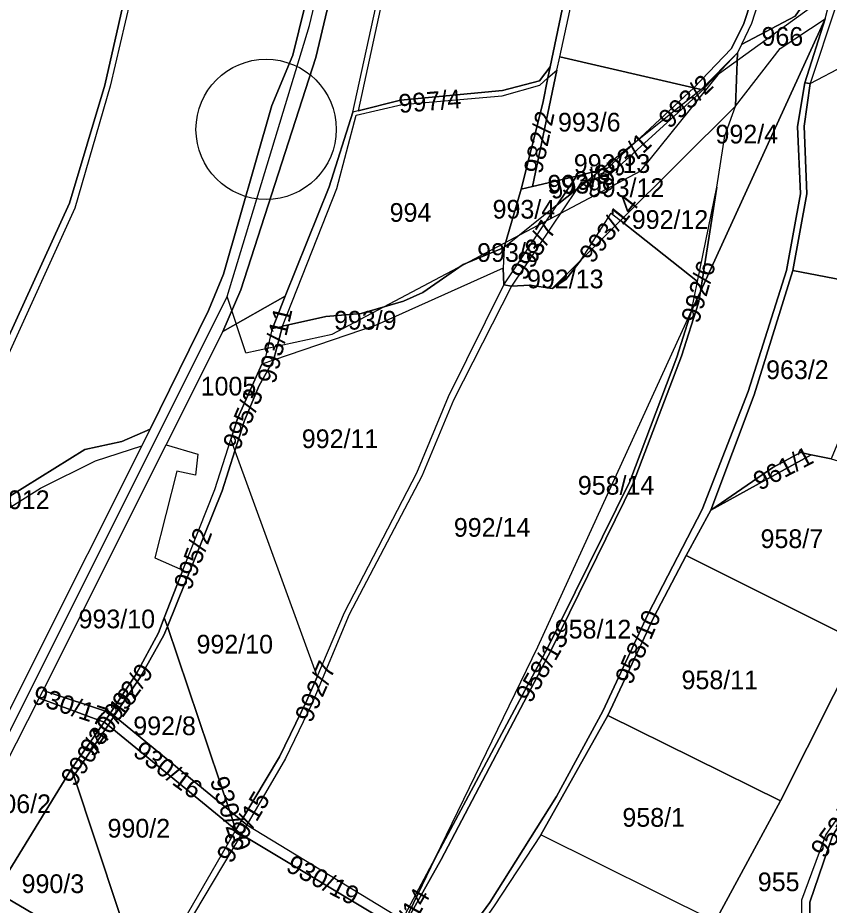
# Model space of a CAD drawing. Extents: x -623250 to -619626, y -1079612 to -1075424.
# Drawn here: x -622121.5 to -621687.6, y -1079113.5 to -1078639.2 of the extents above; entities that cross this region are included whole.
import ezdxf

# ---------------------------------------------------------------- set-up
doc = ezdxf.new("R2010")
doc.units = 0
for name, color, linetype in [('Bodové pole k revizi', 7, 'Continuous'), ('Cestní síť', 7, 'Continuous'), ('Hranice šetřená (k_ú_Džbánov - vnitřní obvod)', 7, 'Continuous'), ('Parcela nároku', 7, 'Continuous'), ('Parcelní číslo', 7, 'Continuous'), ('Silnice III_35719', 7, 'Continuous')]:
    doc.layers.add(name, color=color, linetype=linetype)

msp = doc.modelspace()

# ---------------------------------------------------------------- linework, layer by layer
at = {"layer": 'Bodové pole k revizi'}
msp.add_circle((-621988.75, -1078698.85), 37.5, dxfattribs=at)
at = {"layer": 'Cestní síť'}
for p, q in [((-621746.25, -1078668.89), (-621693.23, -1078630.58)), ((-621788.46, -1078720.96), (-621746.25, -1078668.89)), ((-621953.4, -1078808.38), (-621788.46, -1078720.96)), ((-621999.54, -1078818.21), (-622009.59, -1078788.2)), ((-621999.54, -1078818.21), (-621953.4, -1078808.38))]:
    msp.add_line(p, q, dxfattribs=at)
at = {"layer": 'Hranice šetřená (k_ú_Džbánov - vnitřní obvod)'}
for points in [[(-622051.23, -1079158.54), (-622001.9, -1079075.76), (-621918.53, -1079125.72)], [(-622133.2, -1079106.32), (-622055.86, -1079151.87)]]:
    msp.add_lwpolyline(points, dxfattribs=at)
at = {"layer": 'Parcela nároku'}
for points in [[(-621798.7, -1078125.48), (-621844.4, -1078219.47), (-621874.38, -1078283.8), (-621900.59, -1078357.45), (-621904.78, -1078375.94), (-621939.56, -1078517.46), (-621974.55, -1078659.27), (-621985.66, -1078686.13), (-622011.55, -1078776.25), (-622019.48, -1078795.6), (-622050.66, -1078859.01), (-622055.18, -1078868.03), (-622113.39, -1078984.18), (-622171.75, -1079100.51)], [(-621920.88, -1078143.42), (-621992.93, -1078299.5), (-622012.94, -1078348.91), (-622023.83, -1078386.03), (-622051.57, -1078572.25), (-622075, -1078675.16), (-622093.94, -1078738.39), (-622132.06, -1078821.5), (-622164.4, -1078884.44), (-622184.48, -1078918.47), (-622193.37, -1078930.2), (-622224.32, -1078909.51), (-622245.47, -1078895.87), (-622260.65, -1078888.33), (-622247.8, -1078862.64), (-622201.27, -1078777.95), (-622154.33, -1078663.49), (-622142.85, -1078603.35), (-622129.1, -1078527.57), (-622121.6, -1078479.86), (-622105.64, -1078380), (-622059.07, -1078244.77), (-622006.23, -1078130.73)], [(-621536.14, -1078141.02), (-621601.13, -1078271), (-621640.24, -1078349.18), (-621682.14, -1078455.7), (-621692.39, -1078499.68), (-621716.55, -1078591.12), (-621733.53, -1078642.87), (-621740.16, -1078655.75), (-621760.1, -1078676.68), (-621831.78, -1078660.02), (-621818.81, -1078600.9), (-621799.45, -1078520.18), (-621780.85, -1078451.5), (-621768.67, -1078415.18), (-621763.22, -1078400.52), (-621737.43, -1078338.4), (-621720.36, -1078292.56), (-621706.68, -1078264.18), (-621667.8, -1078192.73)], [(-622132.06, -1078821.5), (-622093.94, -1078738.39), (-622075, -1078675.16), (-622051.57, -1078572.25), (-622023.83, -1078386.03), (-622012.94, -1078348.91), (-621992.93, -1078299.5), (-621920.88, -1078143.42)], [(-621917.7, -1078144.04), (-621989.81, -1078300.86), (-622009.81, -1078350.99), (-622020.37, -1078386.11), (-622048.13, -1078572.96), (-622072.14, -1078675.77), (-622091.03, -1078741.03), (-622128.19, -1078823.01)], [(-621915.38, -1078144.86), (-621987.87, -1078301.69), (-622007.96, -1078351.4), (-622018.08, -1078386.56), (-622033.09, -1078484.64), (-622048.13, -1078572.96), (-622072.14, -1078675.77), (-622091.03, -1078741.03), (-622128.19, -1078823.01)], [(-622158.74, -1079098.38), (-622110.04, -1079002.85), (-622107.93, -1078998.74), (-622042.21, -1078867.47), (-622011.88, -1078806.98), (-622002.29, -1078784.69), (-621962.09, -1078660.47), (-621921.42, -1078488.75), (-621894.99, -1078378.08), (-621888.3, -1078355.01), (-621885.08, -1078343.91), (-621863.53, -1078286.56), (-621830.24, -1078215.74), (-621800.25, -1078151.95)], [(-622142.01, -1078904.85), (-622085.75, -1078869.99), (-622065.84, -1078865.65), (-622050.66, -1078859.01), (-622019.48, -1078795.6), (-622011.55, -1078776.25), (-621985.66, -1078686.13), (-621974.55, -1078659.27), (-621939.56, -1078517.46), (-621904.78, -1078375.94), (-621923.56, -1078371.78), (-621935.88, -1078364.97), (-621896.45, -1078279.61), (-621893.72, -1078261.43), (-621874.57, -1078216.88), (-621849.93, -1078182.93)], [(-621673.38, -1078190.19), (-621712.52, -1078262.15), (-621725.93, -1078289.46), (-621734.43, -1078314.47), (-621736.18, -1078319.06), (-621772.93, -1078413.68), (-621784.46, -1078450.78), (-621803.29, -1078519.05), (-621823.3, -1078600.54), (-621836.88, -1078665.49), (-621838.04, -1078671.32), (-621833.28, -1078667.16), (-621831.78, -1078660.02), (-621818.81, -1078600.9), (-621799.45, -1078520.18), (-621780.85, -1078451.5), (-621768.67, -1078415.18), (-621763.22, -1078400.52), (-621722.25, -1078292.55), (-621708.86, -1078263.97), (-621670.16, -1078192.45)], [(-621684.21, -1078633.08), (-621697.9, -1078674.4), (-621700.7, -1078674.01), (-621689.88, -1078639.73), (-621682.64, -1078612.21)], [(-621572.26, -1078636.28), (-621584.71, -1078668.69), (-621592.06, -1078680.24), (-621602.02, -1078707.55), (-621608.59, -1078730.53), (-621617.46, -1078825.31), (-621625.18, -1078859.11), (-621639.04, -1078905.08), (-621650.82, -1078932.47), (-621662.97, -1078969.66), (-621668.08, -1078993.89), (-621668.45, -1079019.15), (-621676.11, -1079060.58), (-621685.97, -1079076.42), (-621698.06, -1079111.98), (-621697.69, -1079138.49)]]:
    msp.add_lwpolyline(points, dxfattribs=at)
for points in [[(-621851, -1078335.41), (-621875.98, -1078412.38), (-621889.02, -1078460.29), (-621914.51, -1078573.82), (-621939.52, -1078688.9), (-621916.93, -1078683.27), (-621862.33, -1078678.06), (-621842.5, -1078672.85), (-621836.88, -1078665.49), (-621823.3, -1078600.54), (-621803.29, -1078519.05), (-621784.46, -1078450.78), (-621772.93, -1078413.68), (-621736.18, -1078319.06), (-621786.12, -1078256.36), (-621808.67, -1078231.35), (-621826.5, -1078270.98), (-621842.49, -1078311.78)], [(-621894.99, -1078378.08), (-621921.42, -1078488.75), (-621962.09, -1078660.47), (-622002.29, -1078784.69), (-622011.88, -1078806.98), (-621978.6, -1078788.09), (-621955.11, -1078729.51), (-621942.41, -1078689.62), (-621916.87, -1078572.97), (-621891.12, -1078458.9), (-621878.16, -1078411.57), (-621853.26, -1078333.49), (-621867.46, -1078311.76), (-621888.3, -1078355.01)], [(-621843.79, -1078311.14), (-621842.49, -1078311.78), (-621851, -1078335.41), (-621875.98, -1078412.38), (-621889.02, -1078460.29), (-621914.51, -1078573.82), (-621939.52, -1078688.9), (-621942.41, -1078689.62), (-621916.87, -1078572.97), (-621891.12, -1078458.9), (-621878.16, -1078411.57), (-621853.26, -1078333.49)], [(-621716.55, -1078591.12), (-621692.39, -1078499.68), (-621682.14, -1078455.7), (-621678.32, -1078456.03), (-621688.19, -1078499.85), (-621713.01, -1078591.84), (-621729.26, -1078642.23), (-621734.51, -1078653.51), (-621736.66, -1078657.94), (-621756.17, -1078677.59), (-621760.1, -1078676.68), (-621740.16, -1078655.75), (-621733.53, -1078642.87)], [(-621678.32, -1078456.03), (-621688.19, -1078499.85), (-621713.01, -1078591.84), (-621729.26, -1078642.23), (-621734.51, -1078653.51), (-621705.92, -1078638.39), (-621694.79, -1078622.32), (-621693.69, -1078604.02), (-621688.23, -1078594.08), (-621676.74, -1078582.76), (-621665.21, -1078560.88), (-621662.89, -1078553.59), (-621659.96, -1078529.07), (-621668.93, -1078457.17), (-621674.85, -1078456.45)], [(-621659.89, -1078641.88), (-621634.19, -1078619.47), (-621563.27, -1078549.01), (-621592.52, -1078630.82), (-621603.36, -1078669.93), (-621611.72, -1078708.1), (-621622.67, -1078748.23), (-621659.71, -1078778.43), (-621673.47, -1078778.15), (-621677.73, -1078797.56), (-621660.27, -1078811.32), (-621677.88, -1078804.44), (-621679.12, -1078795.35), (-621676.5, -1078780.22), (-621707.18, -1078774.3), (-621699.61, -1078733.28), (-621701.12, -1078697.21), (-621697.9, -1078674.4), (-621679.48, -1078664.79)], [(-621693.69, -1078604.02), (-621694.79, -1078622.32), (-621705.92, -1078638.39), (-621734.51, -1078653.51), (-621736.66, -1078657.94), (-621737.8, -1078686.43), (-621713.91, -1078655.66), (-621689.88, -1078639.73), (-621682.64, -1078612.21), (-621678.01, -1078602.15), (-621676.74, -1078582.76), (-621688.23, -1078594.08)], [(-621684.21, -1078633.08), (-621697.9, -1078674.4), (-621679.48, -1078664.79), (-621659.89, -1078641.88), (-621634.19, -1078619.47), (-621628.01, -1078579.6)], [(-621895.17, -1079089.04), (-621836.16, -1078976.93), (-621792.43, -1078887.96), (-621766.57, -1078820.15), (-621757.53, -1078791.64), (-621756.55, -1078785.48), (-621689.88, -1078639.73), (-621700.7, -1078674.01), (-621704.7, -1078697.39), (-621702.94, -1078733.24), (-621710.44, -1078774.25), (-621730.96, -1078839.05), (-621755.54, -1078901.97), (-621784.5, -1078957.71), (-621808.65, -1079009.85), (-621833.45, -1079055.51), (-621869.06, -1079112.05), (-621888.44, -1079138.25), (-621913.94, -1079122.45)], [(-621743.4, -1078702.37), (-621737.8, -1078686.43), (-621713.91, -1078655.66), (-621689.88, -1078639.73), (-621756.55, -1078785.48), (-621747.73, -1078729.74)], [(-621804.3, -1078722.39), (-621817.17, -1078726.47), (-621822.84, -1078731.01), (-621857.59, -1078782.67), (-621847.83, -1078782.19), (-621835.78, -1078783.93), (-621820.34, -1078768.57), (-621804.22, -1078743.71), (-621799.29, -1078747.62), (-621737.8, -1078686.43), (-621736.66, -1078657.94), (-621756.41, -1078678.95)], [(-621809.67, -1078720.46), (-621817.17, -1078726.47), (-621804.3, -1078722.39), (-621756.41, -1078678.95), (-621736.66, -1078657.94), (-621756.17, -1078677.59), (-621791.31, -1078705.75), (-621806.14, -1078719.56)], [(-621846.36, -1078729.47), (-621833.28, -1078667.16), (-621831.78, -1078660.02), (-621760.1, -1078676.68), (-621791.31, -1078705.75), (-621809.67, -1078720.46), (-621822.84, -1078723.82)], [(-621916.93, -1078683.27), (-621939.52, -1078688.9), (-621942.41, -1078689.62), (-621955.11, -1078729.51), (-621978.6, -1078788.09), (-621985.37, -1078805.28), (-621980.07, -1078804.09), (-621950.91, -1078730.51), (-621940.55, -1078691.35), (-621915.93, -1078685.62), (-621862.53, -1078680.96), (-621842.43, -1078675.16), (-621838.04, -1078671.32), (-621836.88, -1078665.49), (-621842.5, -1078672.85), (-621862.33, -1078678.06)], [(-621840.72, -1078684.79), (-621838.04, -1078671.32), (-621833.28, -1078667.16), (-621846.36, -1078729.47), (-621852.4, -1078730.75)], [(-621915.93, -1078685.62), (-621862.53, -1078680.96), (-621842.43, -1078675.16), (-621838.04, -1078671.32), (-621840.72, -1078684.79), (-621852.4, -1078730.75), (-621861.44, -1078761.94), (-621883.45, -1078771.01), (-621905, -1078786.02), (-621915.36, -1078790.74), (-621938, -1078797.3), (-621956.9, -1078798.88), (-621980.07, -1078804.09), (-621950.91, -1078730.51), (-621940.55, -1078691.35)], [(-621710.44, -1078774.25), (-621702.94, -1078733.24), (-621704.7, -1078697.39), (-621700.7, -1078674.01), (-621697.9, -1078674.4), (-621701.12, -1078697.21), (-621699.61, -1078733.28), (-621707.18, -1078774.3), (-621727.78, -1078840.72), (-621750.95, -1078902.37), (-621764.15, -1078926.59), (-621781.51, -1078959.58), (-621805.98, -1079012.11), (-621841.81, -1079075.9), (-621866.77, -1079113.8), (-621885.5, -1079140.85), (-621888.44, -1079138.25), (-621869.06, -1079112.05), (-621833.45, -1079055.51), (-621808.65, -1079009.85), (-621784.5, -1078957.71), (-621755.54, -1078901.97), (-621730.96, -1078839.05)], [(-621791.31, -1078705.75), (-621760.1, -1078676.68), (-621756.17, -1078677.59)], [(-621737.8, -1078686.43), (-621799.29, -1078747.62), (-621758.09, -1078780.24), (-621747.73, -1078729.74), (-621743.4, -1078702.37)], [(-621791.31, -1078705.75), (-621809.67, -1078720.46), (-621806.14, -1078719.56)], [(-621822.84, -1078723.82), (-621809.67, -1078720.46), (-621817.17, -1078726.47), (-621820.49, -1078727.52), (-621822.84, -1078731.01), (-621833.16, -1078739.28)], [(-621846.36, -1078729.47), (-621822.84, -1078723.82), (-621833.16, -1078739.28), (-621861.44, -1078761.94), (-621852.4, -1078730.75)], [(-621817.17, -1078726.47), (-621820.49, -1078727.52), (-621822.84, -1078731.01)], [(-621761.29, -1078795.84), (-621758.09, -1078780.24), (-621747.73, -1078729.74), (-621756.55, -1078785.48)], [(-621861.67, -1078781.98), (-621833.16, -1078739.28), (-621822.84, -1078731.01), (-621857.59, -1078782.67)], [(-621833.16, -1078739.28), (-621861.44, -1078761.94), (-621862.02, -1078773.12), (-621861.67, -1078781.98)], [(-621804.22, -1078743.71), (-621799.29, -1078747.62), (-621820.34, -1078768.57)], [(-621799.29, -1078747.62), (-621820.34, -1078768.57), (-621828.55, -1078779.1), (-621835.78, -1078783.93), (-621847.83, -1078782.19), (-621857.59, -1078782.67), (-621888.57, -1078843.54), (-621905.43, -1078884.15), (-621944.39, -1078958.22), (-621964.14, -1079005.56), (-621978.32, -1079035.05), (-621999.07, -1079070.55), (-621915.9, -1079121.25), (-621898.34, -1079088.41), (-621843.45, -1078975.43), (-621761.29, -1078795.84), (-621758.09, -1078780.24)], [(-621980.07, -1078804.09), (-621956.9, -1078798.88), (-621938, -1078797.3), (-621915.36, -1078790.74), (-621905, -1078786.02), (-621883.45, -1078771.01), (-621861.44, -1078761.94), (-621862.02, -1078773.12), (-621929.98, -1078803.52), (-621984.84, -1078822.21)], [(-621820.34, -1078768.57), (-621835.78, -1078783.93), (-621828.55, -1078779.1)], [(-621862.02, -1078773.12), (-621929.98, -1078803.52), (-621984.84, -1078822.21), (-621992.38, -1078835.71), (-622000.23, -1078854.55), (-622005.41, -1078870.71), (-621961.45, -1078991.4), (-621946.77, -1078957.08), (-621908.18, -1078882.37), (-621891.15, -1078841.57), (-621861.67, -1078781.98)], [(-621727.78, -1078840.72), (-621707.18, -1078774.3), (-621676.5, -1078780.22), (-621679.12, -1078795.35), (-621677.88, -1078804.44), (-621660.27, -1078811.32), (-621686.68, -1078874.96), (-621697.32, -1078872.82), (-621702.97, -1078871.55), (-621717.87, -1078879.58), (-621750.95, -1078902.37)], [(-621891.15, -1078841.57), (-621861.67, -1078781.98), (-621857.59, -1078782.67), (-621888.57, -1078843.54), (-621905.43, -1078884.15), (-621944.39, -1078958.22), (-621964.14, -1079005.56), (-621978.32, -1079035.05), (-621999.07, -1079070.55), (-622001.92, -1079068.21), (-621981.59, -1079034.31), (-621966.9, -1079004.13), (-621961.45, -1078991.4), (-621946.77, -1078957.08), (-621908.18, -1078882.37)], [(-621794.26, -1078887.03), (-621769.15, -1078820.68), (-621761.29, -1078795.84), (-621756.55, -1078785.48), (-621757.53, -1078791.64), (-621766.57, -1078820.15), (-621792.43, -1078887.96), (-621836.16, -1078976.93), (-621895.17, -1079089.04), (-621913.94, -1079122.45), (-621914.66, -1079122.01), (-621898.34, -1079088.41), (-621838.08, -1078975.74)], [(-622026.58, -1078883.61), (-622036.46, -1078881.58), (-622048.23, -1078927.86), (-622033.23, -1078934.54), (-622016.24, -1078891.34), (-622007.66, -1078864.54), (-622003.95, -1078852.96), (-621991.05, -1078824.33), (-621988.69, -1078819.76), (-621985.37, -1078805.28), (-621978.6, -1078788.09), (-622011.88, -1078806.98), (-622042.21, -1078867.47), (-622025.23, -1078872.38)], [(-621898.34, -1079088.41), (-621843.45, -1078975.43), (-621761.29, -1078795.84), (-621769.15, -1078820.68), (-621794.26, -1078887.03), (-621838.08, -1078975.74)], [(-621985.37, -1078805.28), (-621980.07, -1078804.09), (-621984.84, -1078822.21), (-621991.05, -1078824.33), (-621988.69, -1078819.76)], [(-621984.84, -1078822.21), (-621991.05, -1078824.33), (-622003.95, -1078852.96), (-622007.66, -1078864.54), (-622005.41, -1078870.71), (-622000.23, -1078854.55), (-621992.38, -1078835.71)], [(-622085.75, -1078869.99), (-622142.01, -1078904.85), (-622159.39, -1078924.42), (-622196.09, -1078947.58), (-622200, -1078950.05), (-622157.65, -1078929.82), (-622138.45, -1078908.72), (-622109.45, -1078890.7), (-622079.99, -1078876.08), (-622055.18, -1078868.03), (-622050.66, -1078859.01), (-622065.84, -1078865.65)], [(-622200, -1078950.05), (-622157.65, -1078929.82), (-622138.45, -1078908.72), (-622109.45, -1078890.7), (-622079.99, -1078876.08), (-622055.18, -1078868.03), (-622113.39, -1078984.18), (-622171.75, -1079100.51), (-622269.66, -1079066.41), (-622266.09, -1079060.25), (-622264, -1079060.86), (-622230.39, -1079014.76), (-622211.8, -1078982.44)], [(-622048.23, -1078927.86), (-622033.23, -1078934.54), (-622043.23, -1078959.96), (-622046.35, -1078967.9), (-622058.21, -1078990.05), (-622071.93, -1079010.7), (-622107.93, -1078998.74), (-622042.21, -1078867.47), (-622025.23, -1078872.38), (-622026.58, -1078883.61), (-622036.46, -1078881.58)], [(-622033.23, -1078934.54), (-622016.24, -1078891.34), (-622007.66, -1078864.54), (-622005.41, -1078870.71), (-622012.24, -1078892), (-622041.51, -1078964.59), (-622043.23, -1078959.96)], [(-622012.24, -1078892), (-622005.41, -1078870.71), (-621961.45, -1078991.4), (-621966.9, -1079004.13), (-621981.59, -1079034.31), (-622001.92, -1079068.21), (-622008.41, -1079062.88), (-622041.51, -1078964.59)], [(-621750.95, -1078902.37), (-621697.32, -1078872.82), (-621686.68, -1078874.96), (-621660.21, -1078882.79), (-621664.99, -1078915.82), (-621661.27, -1078943.44), (-621666.29, -1078962.8), (-621671.09, -1078973.07), (-621764.15, -1078926.59)], [(-621702.97, -1078871.55), (-621697.32, -1078872.82), (-621750.95, -1078902.37), (-621717.87, -1078879.58)], [(-621805.98, -1079012.11), (-621781.51, -1078959.58), (-621764.15, -1078926.59), (-621671.09, -1078973.07), (-621713.64, -1079057.74)], [(-621671.09, -1078973.07), (-621666.29, -1078962.8), (-621661.27, -1078943.44), (-621657.87, -1078930.32), (-621655.27, -1078931.11), (-621658.1, -1078946.96), (-621665.65, -1078969.71), (-621670.5, -1078994.1), (-621670.91, -1079020.63), (-621678.22, -1079059.82), (-621689.52, -1079075.82), (-621702.49, -1079110.81), (-621702.61, -1079138.31), (-621715.75, -1079175.17), (-621727.1, -1079196.04), (-621770.3, -1079174.14), (-621761.6, -1079147.11), (-621748.68, -1079122.32), (-621713.64, -1079057.74)], [(-621678.22, -1079059.82), (-621689.52, -1079075.82), (-621702.49, -1079110.81), (-621702.61, -1079138.31), (-621715.75, -1079175.17), (-621727.1, -1079196.04), (-621720.64, -1079199.22), (-621708.75, -1079176.95), (-621697.69, -1079138.49), (-621698.06, -1079111.98), (-621685.97, -1079076.42), (-621676.11, -1079060.58), (-621668.45, -1079019.15), (-621668.08, -1078993.89), (-621662.97, -1078969.66), (-621650.82, -1078932.47), (-621655.27, -1078931.11), (-621658.1, -1078946.96), (-621665.65, -1078969.71), (-621670.5, -1078994.1), (-621670.91, -1079020.63)], [(-622058.21, -1078990.05), (-622046.35, -1078967.9), (-622043.23, -1078959.96), (-622041.51, -1078964.59), (-622043.38, -1078969.23), (-622055.83, -1078991.46), (-622069.93, -1079012.34), (-622071.93, -1079010.7)], [(-622043.38, -1078969.23), (-622041.51, -1078964.59), (-622008.41, -1079062.88), (-622069.93, -1079012.34), (-622055.83, -1078991.46)], [(-622110.04, -1079002.85), (-622107.93, -1078998.74), (-622071.93, -1079010.7), (-622075.29, -1079015.62)], [(-622158.74, -1079098.38), (-622110.04, -1079002.85), (-622075.29, -1079015.62), (-622092.87, -1079040.63), (-622133.2, -1079106.32), (-622136.82, -1079112.45)], [(-622071.93, -1079010.7), (-622069.93, -1079012.34), (-622073.26, -1079017.28), (-622075.29, -1079015.62)], [(-622069.93, -1079012.34), (-622008.41, -1079062.88), (-622004.91, -1079073.28), (-622073.26, -1079017.28)], [(-621841.81, -1079075.9), (-621805.98, -1079012.11), (-621713.64, -1079057.74), (-621748.68, -1079122.32)], [(-622075.29, -1079015.62), (-622073.26, -1079017.28), (-622091.59, -1079044.45), (-622092.87, -1079040.63)], [(-622091.59, -1079044.45), (-622073.26, -1079017.28), (-622004.91, -1079073.28), (-622053.55, -1079157.48), (-622055.86, -1079151.87)], [(-622133.2, -1079106.32), (-622092.87, -1079040.63), (-622091.59, -1079044.45), (-622055.86, -1079151.87)], [(-622008.41, -1079062.88), (-622001.92, -1079068.21), (-622004.91, -1079073.28)], [(-622001.92, -1079068.21), (-621999.07, -1079070.55), (-622001.9, -1079075.76), (-622004.91, -1079073.28)], [(-621999.07, -1079070.55), (-621915.9, -1079121.25), (-621918.53, -1079125.72), (-622001.9, -1079075.76)], [(-622053.55, -1079157.48), (-622109.37, -1079286.11), (-622113.01, -1079308.51), (-622111.25, -1079336.82), (-622105.41, -1079382.94), (-622108.69, -1079439.45), (-622106.8, -1079468.8), (-622103.36, -1079469.39), (-622105.02, -1079439.35), (-622101.77, -1079382.7), (-622107.96, -1079336.5), (-622109.8, -1079307.78), (-622105.03, -1079282.13), (-622051.23, -1079158.54), (-622001.9, -1079075.76), (-622004.91, -1079073.28)], [(-622105.02, -1079439.35), (-622101.77, -1079382.7), (-622107.96, -1079336.5), (-622109.8, -1079307.78), (-622105.03, -1079282.13), (-622051.23, -1079158.54), (-622001.9, -1079075.76), (-621918.53, -1079125.72), (-621916.47, -1079126.95), (-621969.93, -1079229.05), (-622044.05, -1079363.46), (-622092.65, -1079471.22), (-622103.36, -1079469.39)], [(-621841.81, -1079075.9), (-621866.77, -1079113.8), (-621885.5, -1079140.85), (-621873.1, -1079151.8), (-621777.15, -1079186.2), (-621770.3, -1079174.14), (-621761.6, -1079147.11), (-621748.68, -1079122.32)], [(-621915.9, -1079121.25), (-621898.34, -1079088.41), (-621914.66, -1079122.01)], [(-622242.74, -1079309.34), (-622285.94, -1079411.42), (-622281.85, -1079431.73), (-622245.27, -1079440.23), (-622232.32, -1079443.63), (-622191.02, -1079454.47), (-622109.37, -1079286.11), (-622053.55, -1079157.48), (-622055.86, -1079151.87), (-622133.2, -1079106.32), (-622136.82, -1079112.45), (-622160.78, -1079149.39), (-622186.54, -1079195.45), (-622208.62, -1079230.51)]]:
    msp.add_lwpolyline(points, close=True, dxfattribs=at)
at = {"layer": 'Silnice III_35719'}
for p, q in [((-621965.58, -1078643.26), (-621902.19, -1078383.36)), ((-622009.59, -1078788.2), (-621965.58, -1078643.26)), ((-622165.24, -1079099.44), (-622009.59, -1078788.2))]:
    msp.add_line(p, q, dxfattribs=at)

# ---------------------------------------------------------------- texts
at = {"layer": 'Parcelní číslo'}
for s, p in [('966', (-621723.88, -1078654.18)), ('993/6', (-621832.69, -1078700.01)), ('992/4', (-621748.47, -1078706.4)), ('993/13', (-621824.23, -1078722.14)), ('993/5', (-621838.29, -1078733.19)), ('993/12', (-621816.72, -1078735.02)), ('994', (-621922.7, -1078748.27)), ('993/4', (-621867.66, -1078746.56)), ('992/12', (-621793.24, -1078752.05)), ('993/8', (-621875.88, -1078769.68)), ('992/13', (-621849.25, -1078783.8)), ('993/9', (-621952.44, -1078805.89)), ('963/2', (-621721.41, -1078832.32)), ('1005', (-622023.75, -1078841.11)), ('992/11', (-621969.67, -1078869.22)), ('958/14', (-621822.07, -1078894.1)), ('1012', (-622134.27, -1078901.82)), ('992/14', (-621888.38, -1078916.6)), ('958/7', (-621724.38, -1078922.64)), ('993/10', (-622089.02, -1078965.52)), ('958/12', (-621834.41, -1078970.99)), ('992/10', (-622025.95, -1078979)), ('958/11', (-621766.62, -1078998.09)), ('992/8', (-622059.76, -1079022.64)), ('1006/2', (-622144.67, -1079064.31)), ('958/1', (-621798.25, -1079071.59)), ('990/2', (-622073.53, -1079077.39)), ('955', (-621725.85, -1079106.04)), ('990/3', (-622119.48, -1079107.03))]:
    msp.add_text(s, height=10, dxfattribs=at).set_placement(p)
for s, rotation, p in [('993/2', 43.5004, (-621773.08, -1078699)), ('997/4', 4.6209, (-621917.52, -1078690.15)), ('982/2', 78.0716, (-621841.36, -1078723.06)), ('993/1', 43.3363, (-621806.23, -1078730.15)), ('993/3', 17.8553, (-621835.89, -1078736.63)), ('993/14', 51.6809, (-621814.33, -1078771.12)), ('993/7', 58.9027, (-621850.31, -1078780.25)), ('992/6', 73.9686, (-621757.46, -1078803.05)), ('993/11', 76.9417, (-621983.84, -1078835.25)), ('995/3', 66.9564, (-622003.14, -1078870.93)), ('961/1', 27.498, (-621724.91, -1078892.19)), ('995/2', 69.4154, (-622029.12, -1078945.74)), ('958/10', 66.8341, (-621793.41, -1078996.22)), ('958/13', 59.8935, (-621847.22, -1079006.03)), ('992/9', 53.6482, (-622068.27, -1079016.09)), ('992/7', 66.2468, (-621964.61, -1079016.56)), ('930/17', 341.6556, (-622114.46, -1079005.24)), ('930/18', 53.915, (-622081.01, -1079034.91)), ('990/4', 55.0382, (-622091.11, -1079050.77)), ('930/16', 323.5734, (-622060.56, -1079033.07)), ('930/20', 288.6945, (-622018.96, -1079046.74)), ('930/15', 59.0362, (-622007.3, -1079091.78)), ('953/1', 53.8754, (-621690.27, -1079088.98)), ('930/19', 332.339, (-621978.77, -1079094.97)), ('930/14', 60.3563, (-621920.94, -1079143.79))]:
    msp.add_text(s, height=10, rotation=rotation, dxfattribs=at).set_placement(p)

doc.saveas('drawing.dxf')
